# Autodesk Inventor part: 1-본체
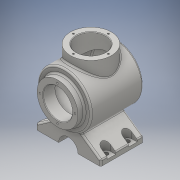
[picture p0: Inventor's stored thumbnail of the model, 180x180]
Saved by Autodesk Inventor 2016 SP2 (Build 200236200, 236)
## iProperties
Created: 2017-04
Part Number: 1-본체
Material: 알루미늄 6061
Document SubType Name: Modeling
Designer: CAMTIC
Density: 2.7 g/cm^3
Appearance: 알루미늄 - 평지
Author: CAMTIC
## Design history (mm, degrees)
sketch "스케치1"
  geometry: L1 (60, 10)-(-60, 10); L2 (-60, 10)-(-60, 0); L3 (-60, 0)-(60, 0); L4 (60, 0)-(60, 10); L5 (60, 10)-(0, 52.012); L6 (0, 52.012)-(-60, 10); 2 further points
  constraints: 12 end point, 2 parallel, 1 coincident, 1 equal length, 1 horizontal, 1 midpoint, 1 perpendicular
  dimensions: "d0" = 120 distance of L2.end L3.end; "d1" = 10 distance of L1.end L2.end; "d2" = 55 deg angle of L6 L2
extrude "돌출1" new body sketch "스케치1" stored distance "d3" = 80; taper "d4" = 0 deg
sketch "스케치4"
  geometry: L1 (48, 132)-(-60, 132); L2 (-60, 132)-(-60, 82); L3 (-60, 82)-(48, 82); L4 (48, 82)-(48, 132); L5 (40, 52.012)-(40, 10) reference; A1 r 113 centre (53, 82) between (-48.336, 132) and (-60, 82); 2 further points
  constraints: 8 end point, 2 parallel, 2 point on circle, 1 centre point, 1 coincident, 1 horizontal, 1 horizontal alignment, 1 perpendicular, 1 point on line, 1 tangent
  dimensions: "d18" = 108 distance of L1.start L1.end; "d19" = 82 distance from line of point (0, 0) L3; "d20" = 8 distance between parallel lines of L4 L5; "d21" = 100 diameter of L1 L3; "d23" = 113 radius of A1
revolve "회전2" sketch "스케치4" stored, may be unused: angle "d24" = 90 deg
node "작업 평면2"
sketch "스케치5"
  geometry: L1 (50, 48)-(-50, 48) reference; C1 r 38 at (0, -2); 1 further point
  constraints: 1 centre point, 1 midpoint, 1 vertical alignment
  dimensions: "d26" = 76 diameter of C1; "d119" = 50 distance from line of C1.centre L1
extrude "돌출3" join sketch "스케치5" distance "d27" = 65; taper "d28" = 0 deg
sketch "스케치7"
  geometry: C1 r 50 at (0, 0) reference; C2 r 38 at (0, 0); 1 further point
  constraints: 1 centre point, 1 coincident
  dimensions: "d35" = 76 diameter of C2
extrude "돌출4" join sketch "스케치7" distance "d36" = 12; taper "d37" = 0 deg
sketch "스케치6"
  geometry: L1 (-40, 32)-(-48.336, 32) reference; L2 (-48.336, 132)-(-40, 132) reference; L3 (-40, 132)-(-40, 147) reference; L4 (-40, 147)-(36, 147) reference; L5 (36, 147)-(36, 132) reference; L6 (36, 132)-(48, 132) reference; L7 (48, 132)-(48, 120) reference; L8 (48, 32)-(40, 32) reference; L9 (40, 32)-(40, 0) reference; L10 (40, 0)-(-40, 0) reference; L11 (-40, 0)-(-40, 32) reference; L12 (-28, 122)-(-41.916, 122); L13 (40, 36.899)-(-40, 36.899) reference; L14 (-28, 122)-(38, 122); L15 (38, 122)-(38, 42); L16 (38, 42)-(-41.916, 42); L17 (38, 82)-(-50, 82); L18 (48, 120)-(60, 120) reference; L19 (60, 120)-(60, 44) reference; L20 (60, 44)-(48, 44) reference; L21 (48, 44)-(48, 32) reference; A1 r 113 centre (53, 82) between (-48.336, 132) and (-48.336, 32) reference; A2 r 103 centre (53, 82) between (-41.916, 122) and (-41.916, 42); 3 further points
  constraints: 10 end point, 4 point on circle, 2 horizontal, 2 midpoint, 1 centre point, 1 horizontal alignment, 1 vertical, 1 other
  dimensions: "d29" = 10 radial gap between concentric circles of A1 A2; "d33" = 80 distance between parallel lines of L16 L14; "d118" = 22 distance between parallel lines of L19 L15
revolve "회전3" sketch "스케치6" stored, may be unused: angle "d34" = 90 deg
hole "구멍1" diameter "d40" = 54; stored, may be unused: countersink angle "d44" = 90 deg, drill point angle "d46" = 118 deg; dims "d38" = 10, "d39" = 10, "d41" = 6, "d42" = 4, "d43" = 2, "d45" = 8
hole "구멍2" diameter "d49" = 54; stored, may be unused: countersink angle "d53" = 90 deg, drill point angle "d55" = 118 deg; dims "d47" = 10, "d48" = 10, "d50" = 6, "d51" = 4, "d52" = 2, "d54" = 8
sketch "스케치8"
  geometry: C1 r 18 at (0, 0); 1 further point
  constraints: 1 centre point, 1 coincident
  dimensions: "d56" = 18 radius of C1
extrude "돌출5" cut sketch "스케치8" stored distance "d57" = 12; taper "d58" = 0 deg
node "작업 평면3"
sketch "스케치12"
  geometry: L1 (60, -19.832)-(50, -19.832); L2 (60, -11.832)-(50, -11.832); L3 (50, -27.832)-(60, -27.832); L4 (60, -39.832)-(60, 40.168) reference; A1 r 8 centre (60, -19.832) between (60, -27.832) and (60, -11.832); A2 r 8 centre (50, -19.832) between (50, -11.832) and (50, -27.832); 2 further points
  constraints: 8 end point, 4 point on circle, 4 tangent, 2 centre point, 1 horizontal, 1 midpoint, 1 parallel, 1 point on line
  dimensions: "d59" = 16 distance between parallel lines of L2 L3; "d61" = 50 horizontal distance of L1.end point (0, 0.168); "d62" = 20 vertical distance of L1.end point (0, 0.168)
node "작업 평면4"
extrude "돌출6" cut sketch "스케치12" stored distance "d64" = 12; taper "d65" = 0 deg
hole "구멍3" diameter "d68" = 8; stored, may be unused: countersink angle "d72" = 90 deg, drill point angle "d74" = 118 deg; dims "d66" = 10, "d67" = 10, "d69" = 6, "d70" = 4, "d71" = 2, "d73" = 8
fillet "모깎기2" dims "d85" = 3
fillet "모깎기3" dims "d86" = 3
chamfer "모따기1" distance "d87" = 1; stored, may be unused: second distance "d88" = 2, angle "d89" = 45 deg
fillet "모깎기4" dims "d90" = 3
fillet "모깎기5" dims "d91" = 3
sketch "스케치13"
  geometry: C1 r 38 at (0, 0) reference; 2 further points
  constraints: 1 vertical alignment
  dimensions: "d92" = 32.5 distance of C1.centre point (0, -32.5)
hole "구멍4" sketch "스케치13" at (0, -32.5) diameter "d93" = 3.242; stored, may be unused: countersink angle "d97" = 90 deg, drill point angle "d99" = 118 deg; dims "d94" = 8, "d95" = 4, "d96" = 2, "d98" = 10
sketch "스케치14"
  geometry: C1 r 38 at (0, 0) reference; 1 further point
  constraints: 1 vertical alignment
  dimensions: "d120" = 32.5 distance of C1.centre point (0, -32.5)
hole "구멍5" sketch "스케치14" at (0, -32.5) diameter "d104" = 3.242; stored, may be unused: countersink angle "d108" = 90 deg, drill point angle "d110" = 118 deg; dims "d105" = 8, "d106" = 4, "d107" = 2, "d109" = 10
node "작업 평면7"
sketch "스케치19"
  geometry: C1 r 50 at (0, 0) reference; 2 further points
  constraints: 1 coincident, 1 other
feature "엠보싱3" sketch "스케치19" dims "d0" = 120, "d1" = 10, "d2" = 55 deg, "d25" = 82, "d121" = 0.5, "d122" = 0
node "솔리드1"
pattern_linear "직사각형 패턴2"
mirror "대칭1"
pattern_circular "원형 패턴1" dims angle "d101" = 360 deg
pattern_circular "원형 패턴2" dims angle "d112" = 360 deg
node "절단 모서리 투영1"
other parameters: "d22" = 113, "d63" = 6
